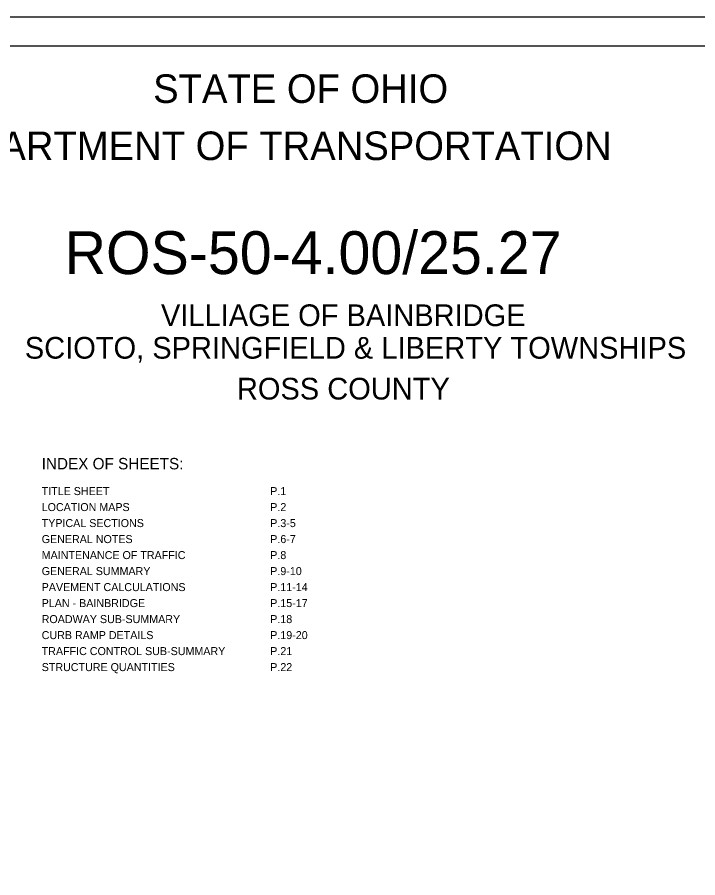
# Model space of a CAD drawing. Extents: x 0 to 34, y -7.5 to 22.
# Drawn here: x 11.42 to 23.33, y 6.94 to 22 of the extents above; entities that cross this region are included whole.
import ezdxf

# ---------------------------------------------------------------- set-up
doc = ezdxf.new("R2010")
doc.units = 0
for name, color, linetype in [('SH_Border', 7, 'Continuous'), ('SH_Cut_Line', 7, 'Continuous'), ('SH_Text', 7, 'Continuous')]:
    doc.layers.add(name, color=color, linetype=linetype)

msp = doc.modelspace()

# ---------------------------------------------------------------- linework, layer by layer
at = {"layer": 'SH_Border'}
msp.add_lwpolyline([(1.5, 21.5), (33.5, 21.5), (33.5, 0.5), (1.5, 0.5)], close=True, dxfattribs=at)
at = {"layer": 'SH_Cut_Line'}
msp.add_lwpolyline([(0, 0), (34, 0), (34, 22), (0, 22)], close=True, dxfattribs=at)

# ---------------------------------------------------------------- texts
at = {"layer": 'SH_Text'}
for s, height, p in [('STATE OF OHIO', 0.5, (13.795, 20.5)), ('DEPARTMENT OF TRANSPORTATION', 0.5, (9.747, 19.5)), ('ROS-50-4.00/25.27', 0.75, (12.246, 17.505)), ('VILLIAGE OF BAINBRIDGE ', 0.38, (13.932, 16.595)), ('SCIOTO, SPRINGFIELD & LIBERTY TOWNSHIPS', 0.38, (11.549, 16.025)), ('ROSS COUNTY', 0.38, (15.261, 15.31)), ('INDEX OF SHEETS:', 0.2, (11.844, 14.088)), ('TITLE SHEET', 0.14, (11.844, 13.638)), ('P.1', 0.14, (15.844, 13.638)), ('LOCATION MAPS', 0.14, (11.844, 13.358)), ('P.2', 0.14, (15.844, 13.358)), ('TYPICAL SECTIONS', 0.14, (11.844, 13.078)), ('P.3-5', 0.14, (15.844, 13.078)), ('GENERAL NOTES', 0.14, (11.844, 12.798)), ('P.6-7', 0.14, (15.844, 12.798)), ('MAINTENANCE OF TRAFFIC', 0.14, (11.844, 12.518)), ('P.8', 0.14, (15.844, 12.518)), ('GENERAL SUMMARY', 0.14, (11.844, 12.238)), ('P.9-10', 0.14, (15.844, 12.238)), ('PAVEMENT CALCULATIONS', 0.14, (11.844, 11.958)), ('P.11-14', 0.14, (15.844, 11.958)), ('PLAN - BAINBRIDGE', 0.14, (11.844, 11.678)), ('P.15-17', 0.14, (15.844, 11.678)), ('ROADWAY SUB-SUMMARY', 0.14, (11.844, 11.398)), ('P.18', 0.14, (15.844, 11.398)), ('CURB RAMP DETAILS', 0.14, (11.844, 11.118)), ('P.19-20', 0.14, (15.844, 11.118)), ('TRAFFIC CONTROL SUB-SUMMARY', 0.14, (11.844, 10.838)), ('P.21', 0.14, (15.844, 10.838)), ('STRUCTURE QUANTITIES', 0.14, (11.844, 10.558)), ('P.22', 0.14, (15.844, 10.558))]:
    msp.add_text(s, height=height, dxfattribs=at).set_placement(p)

doc.saveas('drawing.dxf')
